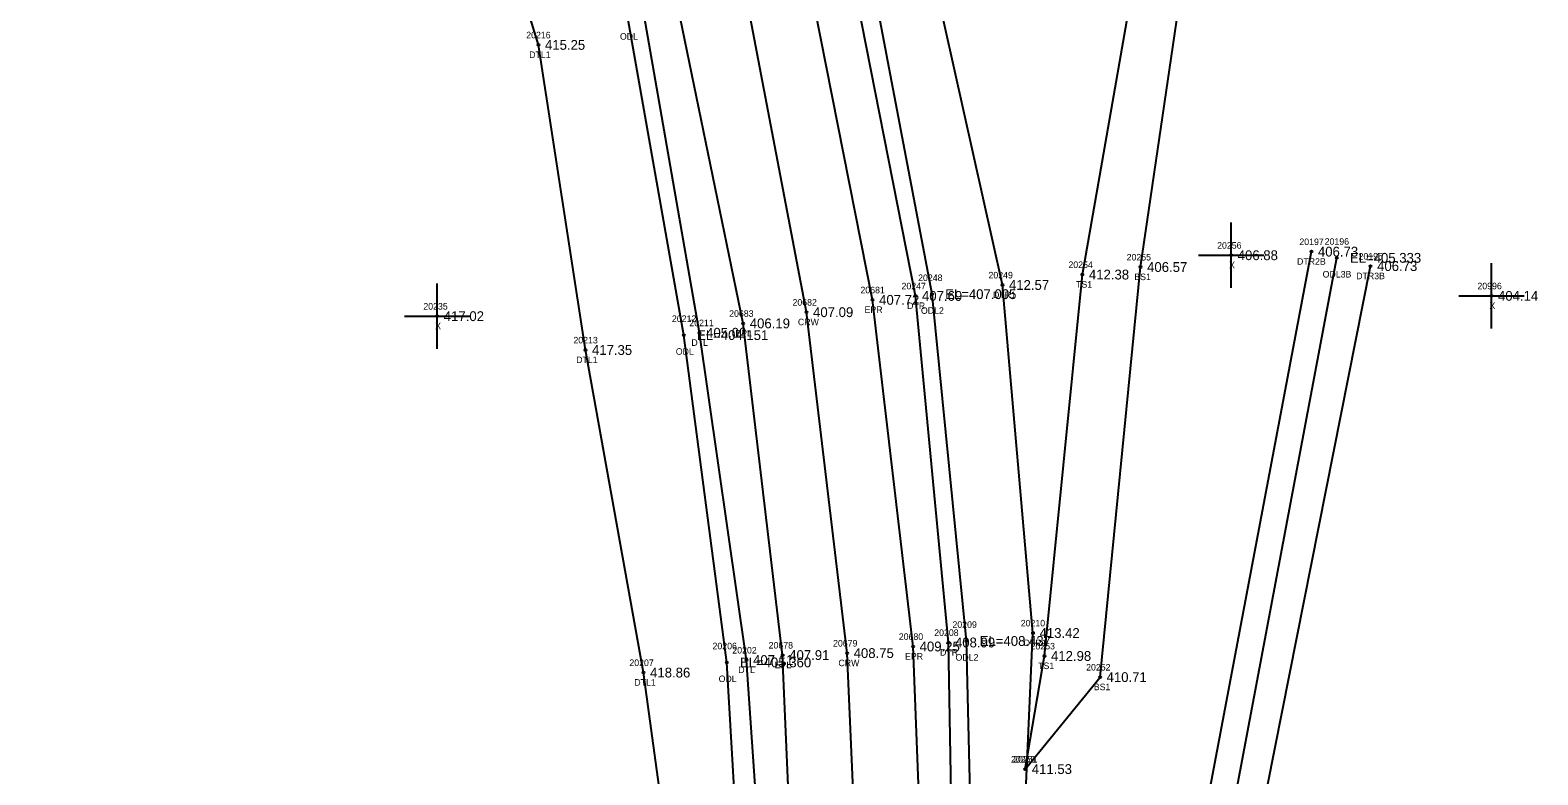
# Model space of a CAD drawing. Extents: x 2186623 to 2187804, y 1079975 to 1082766.
# Drawn here: x 2187544.4 to 2187774.5, y 1080769.7 to 1080883.4 of the extents above; entities that cross this region are included whole.
import ezdxf

# ---------------------------------------------------------------- set-up
doc = ezdxf.new("R2010")
doc.units = 0
for name, color, linetype in [('RD_DTM_BkLn1', 7, 'Continuous'), ('RD_DTM_BkLn2', 7, 'Continuous'), ('RD_DTM_BkLn_txCode', 7, 'Continuous'), ('RD_EX_H2O', 7, 'Continuous'), ('RD_EX_H2O_txCode', 7, 'Continuous'), ('RD_EX_Misc', 7, 'Continuous'), ('RD_EX_Misc_txCode', 7, 'Continuous'), ('RD_EX_Road', 7, 'Continuous'), ('RD_EX_Road_txCode', 7, 'Continuous'), ('RD_EX_TX_H2O_ELEV', 7, 'Continuous'), ('RD_EX_TX_Misc_ELEV', 7, 'Continuous'), ('RD_EX_TX_Road_ELEV', 7, 'Continuous'), ('RD_HC_Survey_ELEV', 7, 'Continuous'), ('RD_HC_Survey_txCode', 7, 'Continuous'), ('RD_SMD_Locator', 7, 'Continuous')]:
    doc.layers.add(name, color=color, linetype=linetype)

msp = doc.modelspace()

# ---------------------------------------------------------------- linework, layer by layer
at = {"layer": 'RD_DTM_BkLn1'}
msp.add_lwpolyline([(2187642.24, 1080529.1), (2187655.35, 1080580.74), (2187664.65, 1080633.05), (2187670.02, 1080686.16), (2187671.29, 1080737.22), (2187669.06, 1080788.31), (2187662.87, 1080840.34), (2187653.68, 1080888.67), (2187640.09, 1080937.32), (2187624.47, 1080981.43), (2187604.07, 1081029.14), (2187583.1, 1081073.79), (2187561.48, 1081119.01), (2187517.22, 1081209.7), (2187473.58, 1081297.58), (2187444.5, 1081356.52)], dxfattribs=at)
at = {"layer": 'RD_DTM_BkLn2'}
for points in [[(2187696.24, 1080770.61), (2187707.66, 1080784.65), (2187713.84, 1080847.23), (2187722.73, 1080907.84), (2187713.23, 1080964.25), (2187712.95, 1080995.78)], [(2187696.24, 1080770.61), (2187699.18, 1080787.87), (2187704.96, 1080846.08), (2187715.45, 1080906.03), (2187700.26, 1080959.54), (2187704.08, 1080990.28)]]:
    msp.add_lwpolyline(points, dxfattribs=at)
at = {"layer": 'RD_EX_H2O'}
for points in [[(2187628.75, 1080548.98), (2187633.55, 1080546.58), (2187640.67, 1080583.21), (2187648.07, 1080635.07), (2187654.41, 1080685.61), (2187657.17, 1080737.23), (2187653.71, 1080787.25), (2187646.55, 1080837.2), (2187638.11, 1080885.61), (2187625.06, 1080933.34), (2187612.25, 1080977.83), (2187603.33, 1080995.47), (2187595.93, 1080992.33), (2187598.15, 1080983.58)], [(2187562.23, 1080319.5), (2187568.42, 1080315.11), (2187580.31, 1080331.23), (2187604.15, 1080372.39), (2187628.61, 1080422.33), (2187648.05, 1080470.41), (2187665.68, 1080522.02), (2187680.31, 1080574.99), (2187687.87, 1080629.9), (2187695.01, 1080683.54), (2187694.9, 1080734.97), (2187697.43, 1080791.38), (2187692.76, 1080844.49), (2187681, 1080897.47), (2187669.05, 1080948.21), (2187658.87, 1080974.63), (2187648.8, 1080980.92), (2187643.49, 1080993.19), (2187638.81, 1080991.77)], [(2187562.23, 1080319.5), (2187571.46, 1080336.44), (2187596.15, 1080376.32), (2187619.89, 1080425.96), (2187640.05, 1080472.96), (2187659.06, 1080523.62), (2187672.26, 1080576.6), (2187680.26, 1080630.9), (2187685.37, 1080684.02), (2187685.51, 1080735.27), (2187684.52, 1080789.93), (2187679.49, 1080842.82), (2187669.29, 1080894.75), (2187655.09, 1080943.38), (2187638.81, 1080991.77)], [(2187565.94, 1080319.75), (2187574.24, 1080334.65), (2187599.82, 1080374.71), (2187622.79, 1080424.73), (2187643.27, 1080471.86), (2187661.54, 1080523.04), (2187675.4, 1080576.09), (2187684.22, 1080630.65), (2187689.37, 1080683.55), (2187688.63, 1080735.08), (2187687.3, 1080790.16), (2187682.02, 1080843.09), (2187672.14, 1080895.26), (2187657.66, 1080944.07), (2187641.89, 1080990.58)], [(2187631.73, 1080551.81), (2187638.31, 1080583.45), (2187646.01, 1080635.33), (2187651.79, 1080685.78), (2187653.6, 1080737.19), (2187650.71, 1080786.89), (2187644.16, 1080836.84), (2187635.64, 1080884.93), (2187623.14, 1080932.78), (2187609.4, 1080976.53), (2187601.6, 1080991.57)], [(2187628.75, 1080548.98), (2187633.64, 1080583.93), (2187643.76, 1080635.97), (2187644.31, 1080686.27), (2187644.6, 1080737.08), (2187638, 1080785.34), (2187629.13, 1080834.57), (2187621.96, 1080881.13), (2187607.49, 1080928.23), (2187601.49, 1080972.93), (2187598.15, 1080983.58)], [(2187687.87, 1080629.9), (2187691.42, 1080639.06), (2187702.45, 1080682.76), (2187718.25, 1080734.91), (2187739.91, 1080849.58)], [(2187687.87, 1080629.9), (2187693.23, 1080639.18), (2187705.36, 1080682.54), (2187722.33, 1080734.64), (2187743.79, 1080848.63)], [(2187687.87, 1080629.9), (2187696.68, 1080638.33), (2187710.57, 1080681.58), (2187726.46, 1080733.9), (2187748.94, 1080847.37)]]:
    msp.add_lwpolyline(points, dxfattribs=at)
at = {"layer": 'RD_EX_Misc'}
for p, q in [((2187727.67, 1080844.03), (2187727.67, 1080854.03)), ((2187722.67, 1080849.03), (2187732.67, 1080849.03)), ((2187767.39, 1080837.83), (2187767.39, 1080847.83)), ((2187606.52, 1080834.73), (2187606.52, 1080844.73)), ((2187762.39, 1080842.83), (2187772.39, 1080842.83)), ((2187601.52, 1080839.73), (2187611.52, 1080839.73))]:
    msp.add_line(p, q, dxfattribs=at)
at = {"layer": 'RD_EX_Road'}
for points in [[(2187651.48, 1080526.2), (2187665.01, 1080578.16), (2187674.62, 1080631.42), (2187679.88, 1080684.75), (2187681.19, 1080736.83), (2187679.13, 1080789.32), (2187672.95, 1080842.22), (2187663.26, 1080891.17), (2187649.84, 1080940.2), (2187633.08, 1080987.22), (2187627.89, 1081000.21), (2187623.73, 1081009.59), (2187612.91, 1081033.05), (2187591.82, 1081078.16), (2187569.84, 1081123.17), (2187525.89, 1081213.51), (2187482.28, 1081301.55), (2187455.91, 1081356.42), (2187456.01, 1081362.23)], [(2187634.28, 1080538.44), (2187635.96, 1080545.92), (2187645.85, 1080582.79), (2187654.89, 1080634.55), (2187660.21, 1080686.53), (2187661.4, 1080737.75), (2187659.23, 1080788.01), (2187653.21, 1080838.63), (2187643.21, 1080887.03), (2187630.24, 1080935.14), (2187614.93, 1080978.89), (2187608.74, 1080993.27), (2187601.62, 1081010.12), (2187595.44, 1081025.31), (2187574.96, 1081069.91), (2187552.71, 1081114.46), (2187508.28, 1081205.07), (2187464.88, 1081292.44), (2187436.83, 1081349.11), (2187432.45, 1081350.83)]]:
    msp.add_lwpolyline(points, dxfattribs=at)
at = {"layer": 'RD_SMD_Locator'}
for centre in [(2187621.96, 1080881.13), (2187727.67, 1080849.03), (2187739.91, 1080849.58), (2187743.79, 1080848.63), (2187704.96, 1080846.08), (2187713.84, 1080847.23), (2187748.94, 1080847.37), (2187682.02, 1080843.09), (2187692.76, 1080844.49), (2187672.95, 1080842.22), (2187679.49, 1080842.82), (2187767.39, 1080842.83), (2187606.52, 1080839.73), (2187653.21, 1080838.63), (2187662.87, 1080840.34), (2187644.16, 1080836.84), (2187646.55, 1080837.2), (2187629.13, 1080834.57), (2187687.3, 1080790.16), (2187697.43, 1080791.38), (2187659.23, 1080788.01), (2187669.06, 1080788.31), (2187679.13, 1080789.32), (2187684.52, 1080789.93), (2187699.18, 1080787.87), (2187650.71, 1080786.89), (2187653.71, 1080787.25), (2187638, 1080785.34), (2187707.66, 1080784.65), (2187696.24, 1080770.61), (2187696.24, 1080770.61)]:
    msp.add_circle(centre, 0.15, dxfattribs=at)

# ---------------------------------------------------------------- texts
at = {"layer": 'RD_DTM_BkLn_txCode'}
for s, p in [('20254', (2187702.84, 1080847.08)), ('20255', (2187711.72, 1080848.23)), ('BS1', (2187712.89, 1080845.23)), ('TS1', (2187704, 1080844.08)), ('20253', (2187697.06, 1080788.87)), ('TS1', (2187698.22, 1080785.87)), ('20252', (2187705.54, 1080785.65)), ('BS1', (2187706.71, 1080782.65)), ('20250', (2187694.08, 1080771.61)), ('20251', (2187694.4, 1080771.61))]:
    msp.add_text(s, height=1, dxfattribs=at).set_placement(p)
at = {"layer": 'RD_EX_H2O_txCode'}
for s, p in [('20216', (2187620.1, 1080882.13)), ('ODL', (2187634.4, 1080881.93)), ('DTL1', (2187620.55, 1080879.13)), ('20197', (2187738.08, 1080850.58)), ('20196', (2187741.94, 1080850.63)), ('DTR2B', (2187737.72, 1080847.58)), ('20195', (2187747.11, 1080848.37)), ('20248', (2187679.9, 1080845.09)), ('20249', (2187690.64, 1080845.49)), ('ODL3B', (2187741.63, 1080845.63)), ('DTR3B', (2187746.75, 1080845.37)), ('20247', (2187677.37, 1080843.82)), ('DTR1', (2187691.33, 1080842.49)), ('DTR', (2187678.22, 1080840.82)), ('ODL2', (2187680.33, 1080840.09)), ('20212', (2187642.33, 1080838.84)), ('20211', (2187644.99, 1080838.2)), ('20213', (2187627.3, 1080835.57)), ('DTL', (2187645.3, 1080835.2)), ('ODL', (2187642.92, 1080833.84)), ('DTL1', (2187627.72, 1080832.57)), ('20209', (2187685.14, 1080792.16)), ('20210', (2187695.56, 1080792.38)), ('20208', (2187682.36, 1080790.93)), ('DTR1', (2187696, 1080789.38)), ('20206', (2187648.53, 1080788.89)), ('20202', (2187651.55, 1080788.25)), ('DTR', (2187683.25, 1080787.93)), ('ODL2', (2187685.61, 1080787.16)), ('20207', (2187635.84, 1080786.34)), ('DTL', (2187652.46, 1080785.25)), ('DTL1', (2187636.59, 1080783.34)), ('ODL', (2187649.46, 1080783.89))]:
    msp.add_text(s, height=1, dxfattribs=at).set_placement(p)
at = {"layer": 'RD_EX_Misc_txCode'}
for s, p in [('20256', (2187725.53, 1080850.03)), ('X', (2187727.35, 1080847.03)), ('20996', (2187765.25, 1080843.83)), ('20235', (2187604.4, 1080840.73)), ('X', (2187767.08, 1080840.83)), ('X', (2187606.2, 1080837.73))]:
    msp.add_text(s, height=1, dxfattribs=at).set_placement(p)
at = {"layer": 'RD_EX_Road_txCode'}
for s, p in [('20681', (2187671.1, 1080843.22)), ('EPR', (2187671.73, 1080840.22)), ('20683', (2187651.07, 1080839.63)), ('EPL', (2187652.01, 1080836.63)), ('20680', (2187676.95, 1080790.32)), ('20678', (2187657.09, 1080789.01)), ('EPR', (2187677.9, 1080787.32)), ('EPL', (2187658.02, 1080786.01))]:
    msp.add_text(s, height=1, dxfattribs=at).set_placement(p)
at = {"layer": 'RD_EX_TX_H2O_ELEV'}
for s, p in [('415.25', (2187622.96, 1080880.38)), ('406.73', (2187740.91, 1080848.83)), ('EL=405.333', (2187745.79, 1080847.88)), ('406.73', (2187749.94, 1080846.62)), ('407.69', (2187680.49, 1080842.07)), ('EL=407.005', (2187684.02, 1080842.34)), ('412.57', (2187693.76, 1080843.74)), ('EL=404.151', (2187646.16, 1080836.09)), ('405.02', (2187647.55, 1080836.45)), ('417.35', (2187630.13, 1080833.82)), ('408.99', (2187685.52, 1080789.18)), ('EL=408.437', (2187689.3, 1080789.41)), ('413.42', (2187698.43, 1080790.63)), ('407.11', (2187654.71, 1080786.5)), ('418.86', (2187639, 1080784.59)), ('EL=405.360', (2187652.71, 1080786.14))]:
    msp.add_text(s, height=1.5, dxfattribs=at).set_placement(p)
at = {"layer": 'RD_EX_TX_Misc_ELEV'}
for s, p in [('406.57', (2187714.84, 1080846.48)), ('406.88', (2187728.67, 1080848.28)), ('412.38', (2187705.96, 1080845.33)), ('404.14', (2187768.39, 1080842.08)), ('417.02', (2187607.52, 1080838.98)), ('412.98', (2187700.18, 1080787.12)), ('410.71', (2187708.66, 1080783.9)), ('411.53', (2187697.24, 1080769.86)), ('411.53', (2187697.24, 1080769.86))]:
    msp.add_text(s, height=1.5, dxfattribs=at).set_placement(p)
at = {"layer": 'RD_EX_TX_Road_ELEV'}
for s, p in [('407.72', (2187673.95, 1080841.47)), ('406.19', (2187654.21, 1080837.88)), ('407.91', (2187660.23, 1080787.26)), ('409.25', (2187680.13, 1080788.57))]:
    msp.add_text(s, height=1.5, dxfattribs=at).set_placement(p)
at = {"layer": 'RD_HC_Survey_ELEV'}
for s, p in [('407.09', (2187663.87, 1080839.59)), ('408.75', (2187670.06, 1080787.56))]:
    msp.add_text(s, height=1.5, dxfattribs=at).set_placement(p)
at = {"layer": 'RD_HC_Survey_txCode'}
for s, p in [('20682', (2187660.73, 1080841.34)), ('CRW', (2187661.56, 1080838.34)), ('20679', (2187666.92, 1080789.31)), ('CRW', (2187667.74, 1080786.31))]:
    msp.add_text(s, height=1, dxfattribs=at).set_placement(p)

doc.saveas('drawing.dxf')
